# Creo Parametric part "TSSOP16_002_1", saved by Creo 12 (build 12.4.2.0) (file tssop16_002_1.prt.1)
Units: Custom; MM, KILOGRAM, SECS

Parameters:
  PTC_WM_ITERATION = "0"
  PTC_WM_VERSION = "-.0"
  PTC_WM_LIFECYCLE_STATE = "In Work"
  PTC_WM_LIFECYCLE = "MO_CADDocument"
  PTC_WM_CREATED_BY = "Maximilian Roepper (Z0017RMS: MO)"
  PTC_WM_CREATED_ON = "18-Sep-26 11:36:42 AM"
  PTC_WM_MODIFIED_BY = "Maximilian Roepper (Z0017RMS: MO)"
  PTC_WM_MODIFIED_ON = "18-Sep-26 11:36:46 AM"
  PDMLINKNUMBER = "PDM000071455005"
  PTC_WM_NAME = "tssop16_002_1.prt"
  PTC_WM_NUMBER = "PDM000071455005"

Other parameters: WEIGHT, WEIGHT_FACTOR, WEIGHT_ADD, _MASS_TEMP, _DIFF_TEMP, MC_ERRORS, SUPPLIER

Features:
  1. coordinate system
  2. datum plane "PRT_YZ"
  3. datum plane "PRT_XY"
  4. datum plane "PRT_XZ"
  5. coordinate system
  6. datum axis
  7. datum axis
  8. datum axis
  9. coordinate system
  10. imported feature

Other named items: PRT, SIEMENS_MO, DRW_VIEW_ORG, PRT_X, PRT_Y, PRT_Z, CS0, ROUGH_GROB

Layers: 00_STD_CSYS-KSYS, 01_STD_PLANES-EBENEN, 02_STD_AXES-ACHSEN, 03_STD_CSYS-KSYS, 24_IMPORT_FEAT-IMPORT_KE

Surfaces: 14 plane, 8 cylinder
